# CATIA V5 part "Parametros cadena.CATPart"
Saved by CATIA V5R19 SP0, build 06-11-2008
Part number: Parametros cadena
Publications: "p", "b1", "b2", "d1", "d2", "i1", "i2", "g", "LE", "Z1", "Z2", "GL"
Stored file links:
  E:\Luis\Dropbox\3DIT\Parking\planos\cat 3 dit park8\Cadena\Parametros cadena.CATPart
  E:\Luis\Dropbox\3DIT\Parking\planos\cat 3 dit park8\Cadena\parametroCadena.xls

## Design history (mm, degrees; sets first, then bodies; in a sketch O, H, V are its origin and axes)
Parameters
  P = 625
  b1 = 63.5
  b2 = 50.8
  d1 = 76.2
  d2 = 38.1
  i1 = 101.6
  i2 = 177.8
  g = 50.8
  LE = 600
  Z1 = 10
  Z2 = 10
  GL = 5950
  P.1 = "650" {design table}
  b1.1 = "63,5" {design table}
  b2.1 = "50,8" {design table}
  d1.1 = "76,2" {design table}
  d2.1 = "38,1" {design table}
  i1.1 = "101,6" {design table}
  i2.1 = "177,8" {design table}
  g.1 = "50,8" {design table}
  LE.1 = "800" {design table}
  Z1.1 = "10" {design table}
  Z2.1 = "10" {design table}
  GL.1 = "6550" {design table}
Body1 (main body)
Relations
  design table "Dimenciones", configuration 30, drives P.1, b1.1, b2.1, d1.1, d2.1, i1.1, i2.1, g.1, LE.1, Z1.1, Z2.1, GL.1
